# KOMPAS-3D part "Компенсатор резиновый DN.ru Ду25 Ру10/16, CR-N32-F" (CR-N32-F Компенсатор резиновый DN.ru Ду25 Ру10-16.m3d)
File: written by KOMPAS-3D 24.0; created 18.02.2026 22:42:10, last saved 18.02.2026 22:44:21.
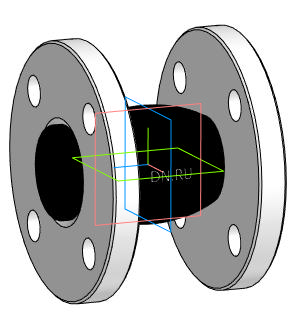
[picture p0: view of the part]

Document properties: Автор: DN.RU; Полное имя файла: D:\PROJECT CAD\DN.RU\...178(2)(ACTUALE). CR-N32-F Компенсатор резиновый DN.ru Ру10-16\CR-N32-F Компенсатор резиновый DN.ru Ру10-16\DN25\CR-N32-F Компенсатор резиновый DN.ru Ду25 Ру10-16.m3d

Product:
- Body: Твердое тело2  | qty 1
    Масса: 2.501783
- Part/product: Компенсатор резиновый DN.ru Ду25 Ру10/16  | designation CR-N32-F
    Масса: 2
    Раздел спецификации: Прочие изделия
    Комментарий: D140-02388
    Примечание: D140-02373
    additional columns: Типовые

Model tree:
1. Твердое тело2  (labels: Твердое тело2)

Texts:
  CR-N32-F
